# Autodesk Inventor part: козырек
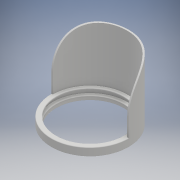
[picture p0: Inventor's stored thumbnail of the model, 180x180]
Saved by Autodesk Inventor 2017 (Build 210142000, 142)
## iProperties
Part Number: козырек
Material: Типовые
Document SubType Name: Modeling
Designer: Система Знаний
Density: 1 g/cm^3
Appearance: По умолчанию
Author: Система Знаний
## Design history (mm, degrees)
sketch "Эскиз1"
  geometry: C1 r 55 at (0, 0); C2 r 57.5 at (0, 0); 1 further point
  constraints: 2 centre point, 2 coincident
  dimensions: "d0" = 110 diameter of C1; "d1" = 115 diameter of C2
extrude "Выдавливание1" new body sketch "Эскиз1" distance "d2" = 4; taper "d3" = 0 deg
sketch "Эскиз2"
  geometry: C1 r 55 at (0, 0) reference; C2 r 63 at (0, 0); C3 r 55 at (0, 0); 1 further point
  constraints: 2 centre point, 2 coincident
  dimensions: "d4" = 126 diameter of C2
extrude "Выдавливание2" join sketch "Эскиз2" distance "d5" = 2.5; taper "d6" = 0 deg
sketch "Эскиз3"
  geometry: C1 r 63 at (0, 0); C2 r 60.5 at (0, 0); 1 further point
  constraints: 2 centre point, 2 coincident
  dimensions: "d7" = 121 diameter of C2
extrude "Выдавливание3" join sketch "Эскиз3" distance "d8" = 8; taper "d9" = 0 deg
sketch "Эскиз4"
  geometry: C1 r 63 at (0, 0) reference; C2 r 63 at (0, 0); C3 r 55 at (0, 0); 1 further point
  constraints: 2 centre point, 2 coincident, 1 concentric
  dimensions: "d10" = 110 diameter of C3
extrude "Выдавливание4" join sketch "Эскиз4" distance "d11" = 2.5; taper "d12" = 0 deg
sketch "Эскиз5"
  geometry: L1 (-63, 0)-(-60.5, 0); L2 (60.5, 0)-(63, 0); A1 r 63 centre (0, 0) between (63, 0) and (-63, 0) reference; A2 r 63 centre (0, 0) between (63, 0) and (-63, 0); A3 r 60.5 centre (0, 0) between (60.5, 0) and (-60.5, 0) reference; A4 r 60.5 centre (0, 0) between (60.5, 0) and (-60.5, 0); 1 further point
  constraints: 8 point on circle, 4 end point, 2 centre point, 1 collinear, 1 horizontal
extrude "Выдавливание5" join sketch "Эскиз5" distance "d13" = 90; taper "d14" = 0 deg
fillet "Сопряжение1" dims "d15" = 60
fillet "Сопряжение2" dims "d16" = 60
fillet "Сопряжение3" dims "d17" = 1
fillet "Сопряжение4" dims "d18" = 1
node "Твердое тело1"
